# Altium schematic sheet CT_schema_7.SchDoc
size 284 x 172 mm
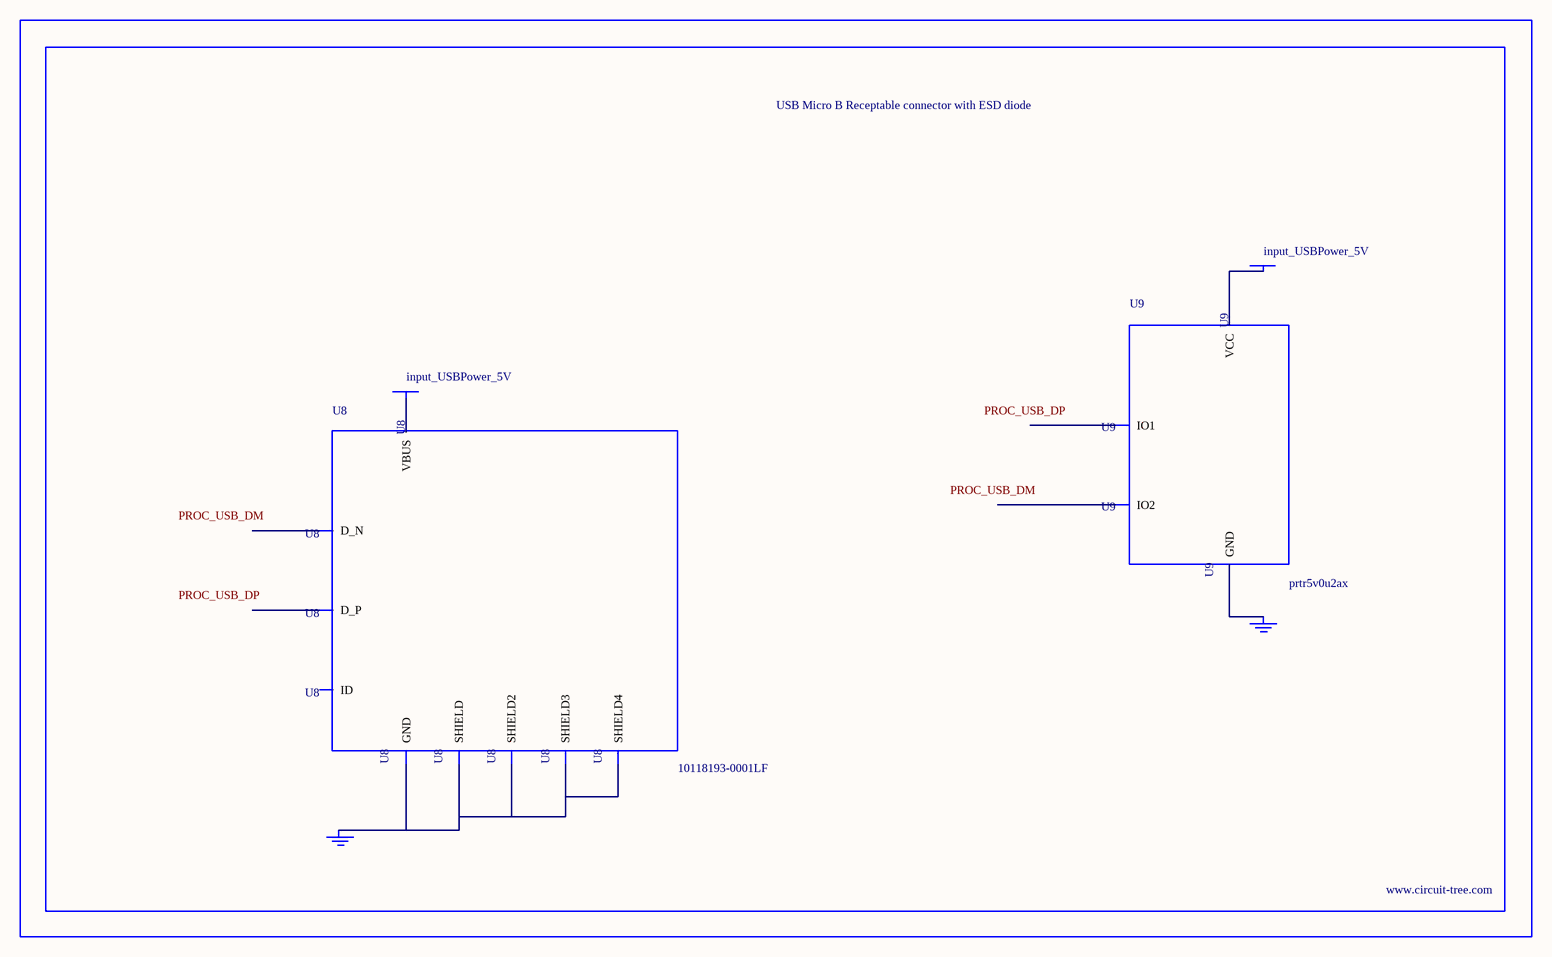
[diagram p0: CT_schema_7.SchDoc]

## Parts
BORDER6  (no value)
GND_INSTANCE_6_0  (no value)
GND_INSTANCE_6_1  (no value)
POWER_INSTANCE_6_0  input_USBPower_5V
POWER_INSTANCE_6_1  input_USBPower_5V
U8  10118193-0001LF  [FCI_10118193-0001LF]
U9  prtr5v0u2ax  [SOT143B]

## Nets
NetGND_INSTANCE_6_0_0: GND_INSTANCE_6_0.0(GND) U8.5(GND) U8.6(SHIELD) U8.7(SHIELD2) U8.8(SHIELD3) U8.9(SHIELD4)
NetGND_INSTANCE_6_1_0: GND_INSTANCE_6_1.0(GND) U9.1(GND)
NetPOWER_INSTANCE_6_0_0: POWER_INSTANCE_6_0.0(PWR) U8.1(VBUS)
NetPOWER_INSTANCE_6_1_0: POWER_INSTANCE_6_1.0(PWR) U9.4(VCC)

Not connected (* = marked no-connect by the designer): U8 2(D_N) 3(D_P) 4(ID); U9 2(IO1) 3(IO2)

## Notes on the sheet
- Labels drawn without touching a wire or pin: PROC_USB_DM, PROC_USB_DP

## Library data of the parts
BORDER6 = BORDER_PAGE6
GND_INSTANCE_6_0 GND_INSTANCE_6_1 = GND
POWER_INSTANCE_6_0 POWER_INSTANCE_6_1 = PWR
